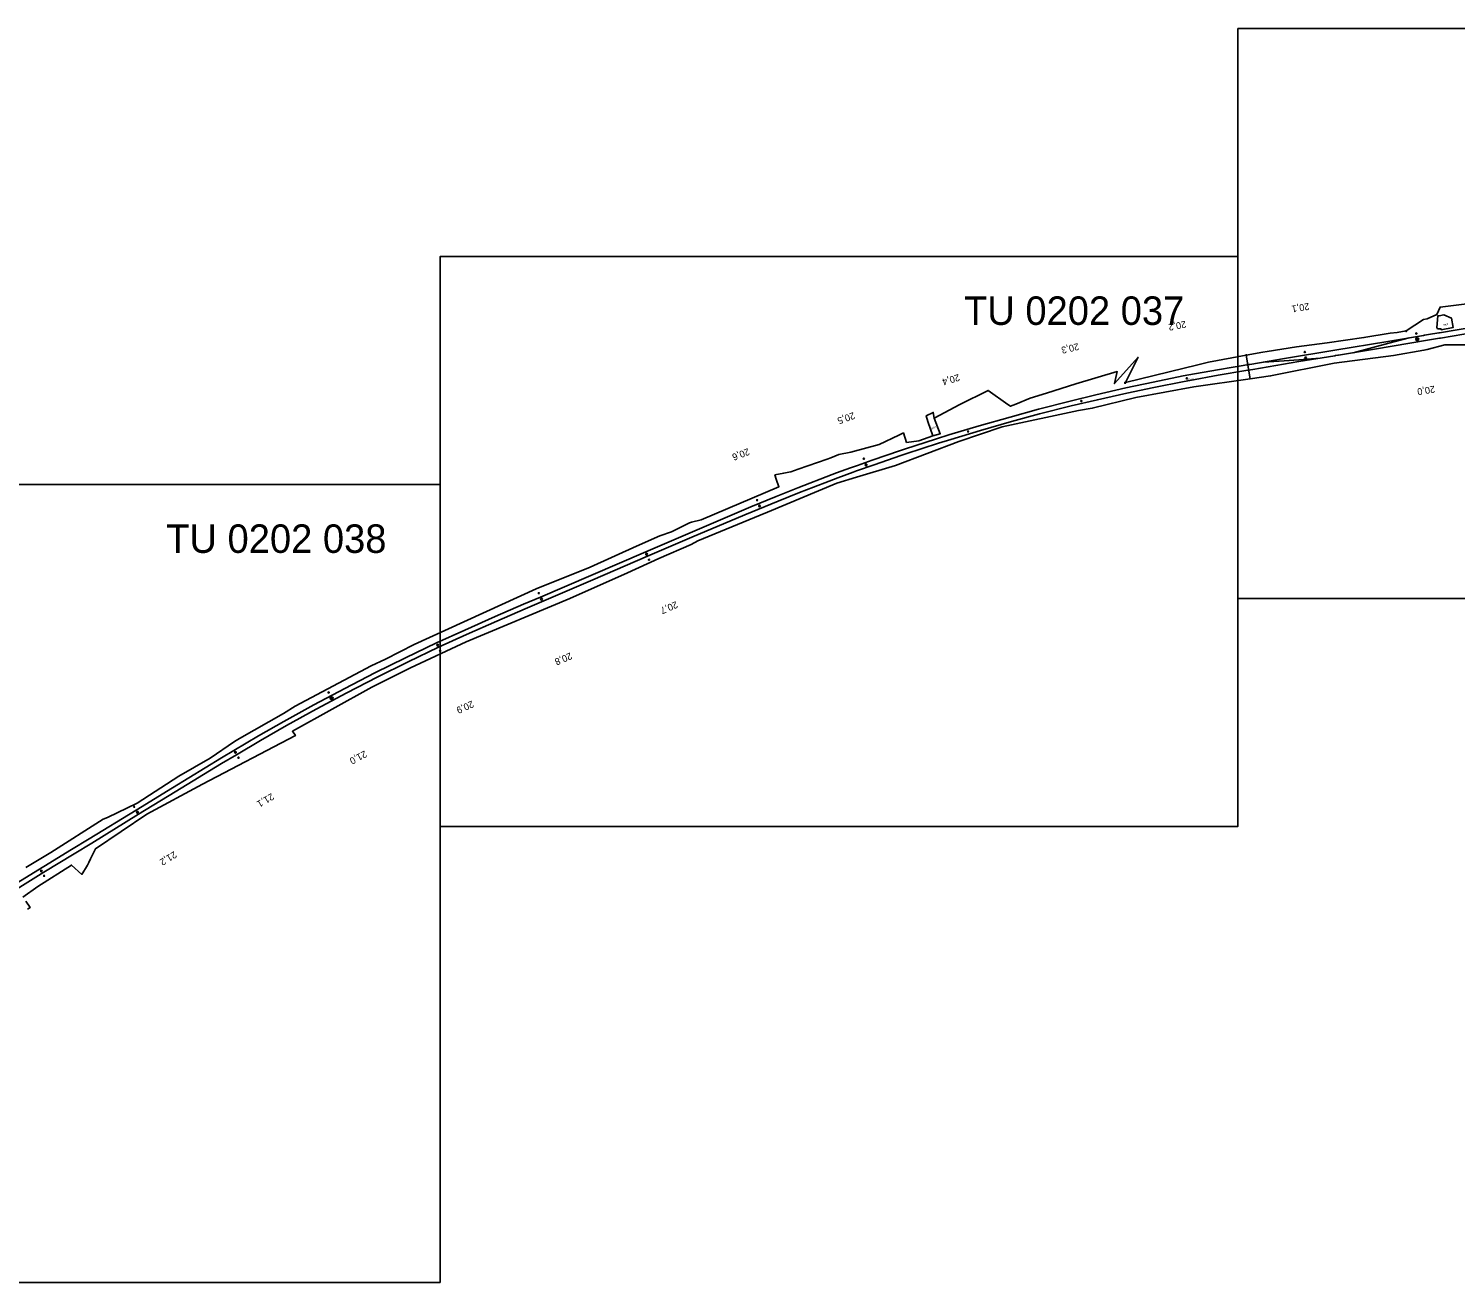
# Model space of a CAD drawing. Extents: x -768800 to -748700, y -1061452 to -1051366.
# Drawn here: x -756261 to -755009, y -1060200 to -1059100 of the extents above; entities that cross this region are included whole.
import ezdxf

# ---------------------------------------------------------------- set-up
doc = ezdxf.new("R2010")
doc.units = 0
for name, color, linetype in [('Vrstva 1', 7, 'Continuous'), ('Vrstva 2', 7, 'Continuous'), ('Vrstva 53', 7, 'Continuous'), ('Vrstva 55', 7, 'Continuous'), ('Vrstva 57', 7, 'Continuous'), ('Vrstva 7', 7, 'Continuous')]:
    doc.layers.add(name, color=color, linetype=linetype)

msp = doc.modelspace()

# ---------------------------------------------------------------- linework, layer by layer
at = {"layer": 'Vrstva 1'}
for p, q in [((-755049.7, -1059371.3), (-755067.7, -1059376.1)), ((-755159.4, -1059391.4), (-755177.2, -1059392.6)), ((-755586, -1059502.8), (-755605, -1059510.4)), ((-755584.5, -1059507), (-755603.4, -1059514.5))]:
    msp.add_line(p, q, dxfattribs=at)
for points in [[(-755200, -1059600), (-755200, -1059100), (-754500, -1059100), (-754500, -1059600), (-755200, -1059600)], [(-755900, -1059800), (-755900, -1059300), (-755200, -1059300), (-755200, -1059800), (-755900, -1059800)], [(-754992.2, -1059361.8), (-755023, -1059366.9), (-755023.6, -1059367), (-755032.8, -1059368.5), (-755036.3, -1059369.1), (-755037, -1059369.3), (-755068.5, -1059374.5), (-755114.8, -1059382.2), (-755159.2, -1059389.6), (-755189.5, -1059394.6), (-755190.7, -1059394.8), (-755192.1, -1059395), (-755197, -1059395.8), (-755204.1, -1059397), (-755218, -1059399.4), (-755243.1, -1059403.9), (-755248, -1059404.8), (-755274.3, -1059410.1), (-755298.3, -1059415.3), (-755324.7, -1059421.4), (-755347.2, -1059426.9), (-755374.8, -1059434), (-755399.7, -1059440.8), (-755427, -1059448.5), (-755453.5, -1059456.5), (-755464.3, -1059459.8), (-755492.6, -1059469), (-755496.1, -1059470.1), (-755520.8, -1059478.6), (-755533.8, -1059483.2), (-755539.8, -1059485.4), (-755552.1, -1059489.9), (-755556, -1059491.3), (-755586, -1059502.8)], [(-754991.6, -1059366.5), (-755022.3, -1059371.6), (-755023, -1059371.7), (-755033.7, -1059373.5), (-755080.2, -1059381.3), (-755111.7, -1059386.5), (-755112.3, -1059386.6), (-755114.3, -1059386.9), (-755114.8, -1059387), (-755146.4, -1059392.2), (-755186.8, -1059399), (-755193.1, -1059400.1), (-755217.3, -1059404.2), (-755242.2, -1059408.7), (-755247.1, -1059409.6), (-755273.6, -1059414.8), (-755297.3, -1059419.8), (-755323.3, -1059425.6), (-755346.4, -1059431.1), (-755374, -1059438.1), (-755398.6, -1059444.8), (-755425.9, -1059452.5), (-755451.9, -1059460.4), (-755462.8, -1059463.8), (-755491.3, -1059473.1), (-755495.7, -1059474.5), (-755519.2, -1059482.6), (-755534.5, -1059488.1), (-755537.5, -1059489.2), (-755551, -1059494.1), (-755558.6, -1059497), (-755572.4, -1059502.3), (-755584.5, -1059507)], [(-755067.7, -1059376.1), (-755081.5, -1059379.7), (-755098.9, -1059384.4)], [(-755127.7, -1059389.1), (-755146.6, -1059390.5), (-755159.4, -1059391.4)], [(-756400, -1060200), (-756400, -1059500), (-755900, -1059500), (-755900, -1060200), (-756400, -1060200)], [(-755605, -1059510.4), (-755627.3, -1059519.6), (-755680.6, -1059542.4), (-755719.5, -1059559.1), (-755767.7, -1059579.7), (-755811.9, -1059598.7), (-755826.9, -1059605.1), (-755851.7, -1059615.9), (-755878.4, -1059627.7), (-755903.2, -1059639), (-755930.4, -1059652), (-755957.2, -1059665.3), (-755983.5, -1059678.9), (-756010.6, -1059693.3), (-756037, -1059707.9), (-756059.2, -1059720.6), (-756080.9, -1059733.3), (-756091.7, -1059739.8), (-756134.7, -1059766), (-756166.6, -1059785.6), (-756207.8, -1059810.8), (-756223.3, -1059820.3), (-756247.6, -1059835.2), (-756275.6, -1059852.3)], [(-755603.4, -1059514.5), (-755632.5, -1059526.5), (-755679, -1059546.3), (-755718, -1059563), (-755766, -1059583.6), (-755807, -1059601.1), (-755825.3, -1059609), (-755850.3, -1059619.8), (-755876.9, -1059631.6), (-755901.3, -1059642.8), (-755928.1, -1059655.6), (-755955.3, -1059669.1), (-755981.7, -1059682.7), (-756008.6, -1059697), (-756034.8, -1059711.5), (-756057.4, -1059724.5), (-756078.6, -1059737), (-756091.7, -1059744.8), (-756132.5, -1059769.7), (-756164.5, -1059789.3), (-756205.6, -1059814.5), (-756221.1, -1059824.1), (-756247.5, -1059840.2), (-756273.4, -1059856.1)]]:
    msp.add_lwpolyline(points, dxfattribs=at)
at = {"layer": 'Vrstva 53'}
for p, q in [((-755052.3, -1059365.4), (-755052.4, -1059365.5)), ((-755192.5, -1059386.5), (-755192.6, -1059386.5)), ((-755299, -1059410.8), (-755298.9, -1059410.8))]:
    msp.add_line(p, q, dxfattribs=at)
for points in [[(-756263.4, -1059835.9), (-756241.4, -1059822.7), (-756195.7, -1059793.7), (-756191.7, -1059792.2), (-756165.8, -1059779.4), (-756129.2, -1059755.9), (-756101.8, -1059740), (-756080.3, -1059725.5), (-756076, -1059722.9), (-756037.4, -1059700.9), (-756027.2, -1059694.5), (-755960.3, -1059659.2), (-755948, -1059653.2), (-755922.7, -1059640.4), (-755815.6, -1059591.5), (-755768.2, -1059572.4), (-755727.5, -1059554.2), (-755707.2, -1059545.1), (-755696.8, -1059541.6), (-755681.2, -1059533.6), (-755679.4, -1059533), (-755670.8, -1059530.9), (-755602.7, -1059501.9), (-755605, -1059495.4), (-755606.2, -1059491.6), (-755598.5, -1059490), (-755593.9, -1059489.1), (-755592.3, -1059488.8), (-755585.7, -1059486.5), (-755560.4, -1059477.9), (-755557.1, -1059476.6), (-755550.2, -1059473.7), (-755539.7, -1059471.6), (-755514.6, -1059465), (-755497.5, -1059456.8), (-755493.4, -1059454.8), (-755490.7, -1059463.1), (-755479.8, -1059461.7), (-755467.6, -1059457.4), (-755471.9, -1059444.7), (-755473.5, -1059439.8), (-755467.3, -1059436.7), (-755466.4, -1059441.8), (-755444, -1059429.7), (-755419, -1059417.5), (-755401.8, -1059429.7), (-755399.4, -1059431.4), (-755394.7, -1059429.4), (-755382.2, -1059424.2), (-755368, -1059419.8), (-755342.1, -1059411.8), (-755305.9, -1059400.9), (-755308.3, -1059411.4), (-755287.5, -1059388.3), (-755298.6, -1059410.6), (-755235.1, -1059395), (-755225.7, -1059392.7), (-755192.6, -1059386.5), (-755178.1, -1059383.8), (-755174.3, -1059383.3), (-755148.5, -1059379.3), (-755121.7, -1059375.6), (-755089.4, -1059371.1), (-755066.3, -1059367.2), (-755060.3, -1059366.6), (-755052.4, -1059365.3), (-755037.2, -1059355.2), (-755034, -1059354.7), (-755025.3, -1059350.8), (-755022.6, -1059344.4), (-754961.3, -1059336.9)], [(-755000.3, -1059377.4), (-755018.5, -1059377.6), (-755033.9, -1059381.5), (-755036.7, -1059382.2), (-755063.6, -1059386.7), (-755115.5, -1059393.5), (-755171.3, -1059404.7), (-755189.1, -1059407.2), (-755238.6, -1059414.2), (-755289.4, -1059423.7), (-755327.7, -1059433.1), (-755339.8, -1059435.2), (-755406.9, -1059449.4), (-755444.8, -1059462.2), (-755500.3, -1059483.4), (-755534.7, -1059493.7), (-755551.9, -1059498.9), (-755612.7, -1059524.3), (-755619.2, -1059527), (-755673.7, -1059549.5), (-755679.6, -1059552.7), (-755708, -1059564.9), (-755735.6, -1059577.6), (-755786, -1059599.9), (-755877, -1059638), (-755925.9, -1059660.7), (-755959.9, -1059677.9), (-756029.5, -1059716.4), (-756026.9, -1059720.2), (-756108.5, -1059762.8), (-756157.3, -1059789.1), (-756202.4, -1059819.6), (-756206.7, -1059828.4), (-756208.2, -1059831.6), (-756209.3, -1059833.9), (-756214.3, -1059842), (-756223.3, -1059833.8), (-756253, -1059852.5), (-756266, -1059861.9)], [(-756263.5, -1059865.4), (-756259.5, -1059871), (-756262.1, -1059872.6)]]:
    msp.add_lwpolyline(points, dxfattribs=at)
for centre in [(-755052.3, -1059365.4), (-755192.5, -1059386.5), (-755298.9, -1059410.8)]:
    msp.add_circle(centre, 0.499, dxfattribs=at)
at = {"layer": 'Vrstva 55'}
msp.add_line((-755189.1, -1059407.2), (-755192.6, -1059386.5), dxfattribs=at)
for points in [[(-755021.6, -1059364.2), (-755021.8, -1059363.4), (-755024.8, -1059363.4), (-755025.3, -1059362.2), (-755024.6, -1059352.1), (-755023.5, -1059351.9), (-755019.4, -1059351.2), (-755012.6, -1059354), (-755011, -1059362.2), (-755021.6, -1059364.2)], [(-755466.4, -1059441.8), (-755461.1, -1059455.5), (-755467.6, -1059457.4)]]:
    msp.add_lwpolyline(points, dxfattribs=at)
at = {"layer": 'Vrstva 7'}
for p, q in [((-755043.3, -1059367.5), (-755043.4, -1059367.5)), ((-755141.3, -1059383.7), (-755141.4, -1059383.7)), ((-755244.8, -1059406.8), (-755244.9, -1059406.8)), ((-755337.3, -1059426.8), (-755337.4, -1059426.8)), ((-755436.6, -1059453.5), (-755436.6, -1059453.5)), ((-755528.1, -1059477.3), (-755528.2, -1059477.3)), ((-755621.7, -1059513.7), (-755621.8, -1059513.7)), ((-755716.6, -1059566), (-755716.7, -1059566)), ((-755813.3, -1059595.3), (-755813.4, -1059595.3)), ((-755899.9, -1059645.6), (-755899.9, -1059645.7)), ((-755997.6, -1059682.5), (-755997.7, -1059682.5)), ((-756076.7, -1059739.6), (-756076.8, -1059739.6)), ((-756168.3, -1059782.8), (-756168.4, -1059782.8)), ((-756247.2, -1059843.3), (-756247.3, -1059843.3))]:
    msp.add_line(p, q, dxfattribs=at)
for centre, radius in [((-755043.4, -1059367.5), 0.5), ((-755042.6, -1059372.6), 1.25), ((-755042.6, -1059372.6), 0.752), ((-755141.3, -1059383.7), 0.5), ((-755140.5, -1059388.9), 0.75), ((-755244.8, -1059406.8), 0.5), ((-755337.3, -1059426.8), 0.5), ((-755436.6, -1059453.5), 0.5), ((-755528.2, -1059477.3), 0.5), ((-755526.2, -1059482.8), 0.75), ((-755621.8, -1059513.7), 0.5), ((-755619.7, -1059518.8), 0.75), ((-755718.8, -1059561.1), 0.75), ((-755716.7, -1059566), 0.5), ((-755813.3, -1059595.3), 0.5), ((-755811, -1059600.6), 0.75), ((-755902.1, -1059640.9), 0.75), ((-755899.9, -1059645.7), 0.5), ((-755997.7, -1059682.5), 0.5), ((-755995.1, -1059687.4), 1.25), ((-755995.1, -1059687.4), 0.752), ((-756079.5, -1059735), 0.75), ((-756076.8, -1059739.6), 0.5), ((-756168.3, -1059782.8), 0.5), ((-756165.5, -1059787.5), 0.75), ((-756249.8, -1059839.1), 0.75), ((-756247.3, -1059843.3), 0.5)]:
    msp.add_circle(centre, radius, dxfattribs=at)

# ---------------------------------------------------------------- texts
at = {"layer": 'Vrstva 2'}
for s, p in [('TU 0202 037', (-755440.3, -1059360)), ('TU 0202 038', (-756140.3, -1059560))]:
    msp.add_text(s, height=25, dxfattribs=at).set_placement(p)
at = {"layer": 'Vrstva 57'}
for s, rotation, p in [('1996', 189.9327, (-755015.6, -1059358.6)), ('1916/3', 186.048, (-755238.3, -1059406.7)), ('1896/1', 203.9765, (-755465, -1059448.5))]:
    msp.add_text(s, height=1.5, rotation=rotation, dxfattribs=at).set_placement(p)
at = {"layer": 'Vrstva 7'}
for s, rotation, p in [('20,1', 189.4095, (-755137.8, -1059340.7)), ('20,2', 190.6358, (-755246, -1059356.4)), ('20,3', 193.3995, (-755340.2, -1059375.9)), ('20,4', 196.7879, (-755445.1, -1059403)), ('20,0', 189.4567, (-755027.6, -1059413.3)), ('20,5', 199.6404, (-755537.3, -1059436.4)), ('20,6', 201.2886, (-755629.8, -1059468)), ('20,7', 203.1784, (-755693, -1059602.2)), ('20,8', 203.1927, (-755785.7, -1059647.2)), ('20,9', 204.6616, (-755872.1, -1059689.4)), ('21,0', 208.0509, (-755966.2, -1059733.2)), ('21,1', 210.5024, (-756047.9, -1059770.5)), ('21,2', 211.4788, (-756133.3, -1059821.4))]:
    msp.add_text(s, height=6, rotation=rotation, dxfattribs=at).set_placement(p)

doc.saveas('drawing.dxf')
